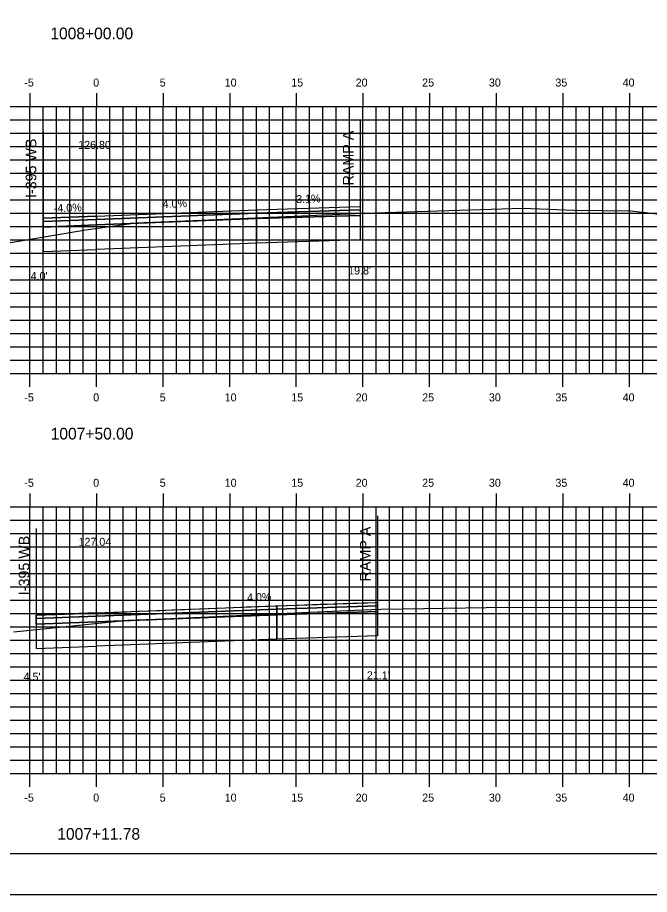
# Model space of a CAD drawing. Extents: x 851738 to 851910, y 365624 to 365734.
# Drawn here: x 851815.6 to 851863, y 365624 to 365689.7 of the extents above; entities that cross this region are included whole.
import ezdxf

# ---------------------------------------------------------------- set-up
doc = ezdxf.new("R2010")
doc.units = 0
for name, color, linetype in [('ANNOTATION', 7, 'Continuous'), ('BORDER', 7, 'Continuous'), ('D_Roadway_Centerline', 7, 'Continuous'), ('D_Roadway_Centerline_Text', 7, 'Continuous'), ('D_Roadway_Edge_Shoulder', 7, 'Continuous'), ('D_Roadway_Edge_TW', 7, 'Continuous'), ('D_Roadway_FinishedGrade', 7, 'Continuous'), ('D_Roadway_Pavement', 7, 'Continuous'), ('D_Roadway_SubGrade', 7, 'Continuous'), ('D_Text_Standard', 7, 'Continuous'), ('H_V ANNOTATION', 7, 'Continuous'), ('M_Roadway_Centerline', 7, 'Continuous'), ('MAJOR', 7, 'Continuous'), ('MINOR', 7, 'Continuous'), ('PLOT BOUNDARY', 7, 'Continuous'), ('S_Roadway_Centerline', 7, 'Continuous')]:
    doc.layers.add(name, color=color, linetype=linetype)

msp = doc.modelspace()

# ---------------------------------------------------------------- linework, layer by layer
at = {"layer": 'BORDER'}
msp.add_lwpolyline([(851746.522, 365627.027), (851906.522, 365627.027), (851906.522, 365732.027), (851746.522, 365732.027)], close=True, dxfattribs=at)
at = {"layer": 'D_Roadway_Centerline'}
for points in [[(851817.522, 365674.663), (851817.522, 365674.663), (851821.522, 365674.823), (851821.528, 365674.823), (851833.522, 365675.294), (851841.32, 365675.536)], [(851817.001, 365644.893), (851819.848, 365645.005), (851821.522, 365645.071), (851821.93, 365645.087), (851821.995, 365645.09), (851823.785, 365645.16), (851824.146, 365645.174), (851824.644, 365645.194), (851826.3, 365645.26), (851827.19, 365645.295), (851827.835, 365645.32), (851828.153, 365645.333), (851828.459, 365645.345), (851829.366, 365645.381), (851830.621, 365645.43), (851832.354, 365645.499), (851832.787, 365645.516), (851834.936, 365645.601), (851834.957, 365645.602), (851834.973, 365645.603), (851835.071, 365645.606), (851836.662, 365645.66), (851837.131, 365645.676), (851838.347, 365645.717), (851839.308, 365645.748), (851840.038, 365645.773), (851841.49, 365645.819), (851841.736, 365645.827), (851842.605, 365645.855)]]:
    msp.add_lwpolyline(points, dxfattribs=at)
at = {"layer": 'D_Roadway_Edge_Shoulder'}
for points in [[(851821.522, 365674.823), (851817.522, 365674.663), (851817.522, 365674.413), (851821.522, 365674.573)], [(851821.522, 365645.071), (851817.001, 365644.893), (851817.001, 365644.643), (851821.522, 365644.821)]]:
    msp.add_lwpolyline(points, close=True, dxfattribs=at)
at = {"layer": 'D_Roadway_Edge_TW'}
for points in [[(851833.522, 365675.294), (851841.32, 365675.536), (851841.32, 365675.286), (851833.522, 365675.044)], [(851821.522, 365674.823), (851833.522, 365675.294), (851833.522, 365675.044), (851821.522, 365674.573)], [(851835.071, 365645.606), (851842.605, 365645.855), (851842.605, 365645.605), (851835.071, 365645.356)], [(851821.522, 365645.071), (851835.071, 365645.606), (851835.071, 365645.356), (851821.522, 365644.821)]]:
    msp.add_lwpolyline(points, close=True, dxfattribs=at)
at = {"layer": 'D_Roadway_FinishedGrade'}
for p, q in [((851841.32, 365675.536), (851841.32, 365675.286)), ((851821.522, 365674.823), (851821.522, 365674.573)), ((851833.522, 365675.294), (851833.522, 365675.044)), ((851817.522, 365674.663), (851817.522, 365674.413)), ((851842.605, 365645.855), (851842.605, 365645.605)), ((851835.071, 365645.606), (851835.071, 365645.356)), ((851817.001, 365644.893), (851817.001, 365644.643)), ((851821.522, 365645.071), (851821.522, 365644.821))]:
    msp.add_line(p, q, dxfattribs=at)
at = {"layer": 'D_Roadway_Pavement'}
for points in [[(851821.522, 365674.573), (851833.522, 365675.044), (851833.522, 365674.627), (851821.522, 365674.156)], [(851833.522, 365675.044), (851841.32, 365675.286), (851841.32, 365674.869), (851833.522, 365674.627)], [(851821.522, 365674.573), (851817.522, 365674.413), (851817.522, 365673.996), (851821.522, 365674.156)], [(851821.522, 365644.821), (851835.071, 365645.356), (851835.071, 365644.939), (851821.522, 365644.404)], [(851835.071, 365645.356), (851842.605, 365645.605), (851842.605, 365645.189), (851835.071, 365644.939)], [(851821.522, 365644.821), (851817.001, 365644.643), (851817.001, 365644.226), (851821.522, 365644.404)]]:
    msp.add_lwpolyline(points, close=True, dxfattribs=at)
at = {"layer": 'D_Roadway_SubGrade'}
for p, q in [((851841.32, 365682.033), (851841.32, 365673.036)), ((851817.522, 365681.16), (851817.522, 365672.163)), ((851842.605, 365652.352), (851842.605, 365643.355)), ((851817.001, 365651.39), (851817.001, 365642.393))]:
    msp.add_line(p, q, dxfattribs=at)
for points in [[(851833.522, 365674.627), (851841.32, 365674.869), (851841.32, 365673.036), (851833.522, 365672.794)], [(851821.522, 365674.156), (851817.522, 365673.996), (851817.522, 365674.496), (851817.522, 365674.663), (851817.522, 365672.163), (851821.522, 365672.323)], [(851821.522, 365674.156), (851833.522, 365674.627), (851833.522, 365672.794), (851821.522, 365672.323)], [(851835.071, 365644.939), (851842.605, 365645.189), (851842.605, 365643.355), (851835.071, 365643.106)], [(851821.522, 365644.404), (851817.001, 365644.226), (851817.001, 365644.726), (851817.001, 365644.893), (851817.001, 365642.393), (851821.522, 365642.571)], [(851821.522, 365644.404), (851835.071, 365644.939), (851835.071, 365643.106), (851821.522, 365642.571)]]:
    msp.add_lwpolyline(points, close=True, dxfattribs=at)
at = {"layer": 'MAJOR'}
for p, q in [((851816.522, 365684.029), (851816.522, 365683.027)), ((851821.522, 365684.029), (851821.522, 365683.027)), ((851826.522, 365684.029), (851826.522, 365683.027)), ((851831.522, 365684.029), (851831.522, 365683.027)), ((851836.522, 365684.029), (851836.522, 365683.027)), ((851841.522, 365684.029), (851841.522, 365683.027)), ((851846.522, 365684.029), (851846.522, 365683.027)), ((851851.522, 365684.029), (851851.522, 365683.027)), ((851856.522, 365684.029), (851856.522, 365683.027)), ((851861.522, 365684.029), (851861.522, 365683.027)), ((851751.522, 365683.027), (851891.522, 365683.027)), ((851751.522, 365683.027), (851891.522, 365683.027)), ((851816.522, 365663.027), (851816.522, 365683.027)), ((851821.522, 365663.027), (851821.522, 365683.027)), ((851826.522, 365663.027), (851826.522, 365683.027)), ((851831.522, 365663.027), (851831.522, 365683.027)), ((851836.522, 365663.027), (851836.522, 365683.027)), ((851841.522, 365663.027), (851841.522, 365683.027)), ((851846.522, 365663.027), (851846.522, 365683.027)), ((851851.522, 365663.027), (851851.522, 365683.027)), ((851856.522, 365663.027), (851856.522, 365683.027)), ((851861.522, 365663.027), (851861.522, 365683.027)), ((851751.522, 365678.027), (851891.522, 365678.027)), ((851751.522, 365673.027), (851891.522, 365673.027)), ((851751.522, 365668.027), (851891.522, 365668.027)), ((851751.522, 365663.027), (851891.522, 365663.027)), ((851751.522, 365663.027), (851891.522, 365663.027)), ((851816.522, 365662.025), (851816.522, 365663.027)), ((851821.522, 365662.025), (851821.522, 365663.027)), ((851826.522, 365662.025), (851826.522, 365663.027)), ((851831.522, 365662.025), (851831.522, 365663.027)), ((851836.522, 365662.025), (851836.522, 365663.027)), ((851841.522, 365662.025), (851841.522, 365663.027)), ((851846.522, 365662.025), (851846.522, 365663.027)), ((851851.522, 365662.025), (851851.522, 365663.027)), ((851856.522, 365662.025), (851856.522, 365663.027)), ((851861.522, 365662.025), (851861.522, 365663.027)), ((851816.522, 365654.029), (851816.522, 365653.027)), ((851821.522, 365654.029), (851821.522, 365653.027)), ((851826.522, 365654.029), (851826.522, 365653.027)), ((851831.522, 365654.029), (851831.522, 365653.027)), ((851836.522, 365654.029), (851836.522, 365653.027)), ((851841.522, 365654.029), (851841.522, 365653.027)), ((851846.522, 365654.029), (851846.522, 365653.027)), ((851851.522, 365654.029), (851851.522, 365653.027)), ((851856.522, 365654.029), (851856.522, 365653.027)), ((851861.522, 365654.029), (851861.522, 365653.027)), ((851751.522, 365653.027), (851891.522, 365653.027)), ((851751.522, 365653.027), (851891.522, 365653.027)), ((851816.522, 365633.027), (851816.522, 365653.027)), ((851821.522, 365633.027), (851821.522, 365653.027)), ((851826.522, 365633.027), (851826.522, 365653.027)), ((851831.522, 365633.027), (851831.522, 365653.027)), ((851836.522, 365633.027), (851836.522, 365653.027)), ((851841.522, 365633.027), (851841.522, 365653.027)), ((851846.522, 365633.027), (851846.522, 365653.027)), ((851851.522, 365633.027), (851851.522, 365653.027)), ((851856.522, 365633.027), (851856.522, 365653.027)), ((851861.522, 365633.027), (851861.522, 365653.027)), ((851751.522, 365648.027), (851891.522, 365648.027)), ((851751.522, 365643.027), (851891.522, 365643.027)), ((851751.522, 365638.027), (851891.522, 365638.027)), ((851751.522, 365633.027), (851891.522, 365633.027)), ((851751.522, 365633.027), (851891.522, 365633.027)), ((851816.522, 365632.025), (851816.522, 365633.027)), ((851821.522, 365632.025), (851821.522, 365633.027)), ((851826.522, 365632.025), (851826.522, 365633.027)), ((851831.522, 365632.025), (851831.522, 365633.027)), ((851836.522, 365632.025), (851836.522, 365633.027)), ((851841.522, 365632.025), (851841.522, 365633.027)), ((851846.522, 365632.025), (851846.522, 365633.027)), ((851851.522, 365632.025), (851851.522, 365633.027)), ((851856.522, 365632.025), (851856.522, 365633.027)), ((851861.522, 365632.025), (851861.522, 365633.027))]:
    msp.add_line(p, q, dxfattribs=at)
at = {"layer": 'MINOR'}
for p, q in [((851817.522, 365663.027), (851817.522, 365683.027)), ((851818.522, 365663.027), (851818.522, 365683.027)), ((851819.522, 365663.027), (851819.522, 365683.027)), ((851820.522, 365663.027), (851820.522, 365683.027)), ((851822.522, 365663.027), (851822.522, 365683.027)), ((851823.522, 365663.027), (851823.522, 365683.027)), ((851824.522, 365663.027), (851824.522, 365683.027)), ((851825.522, 365663.027), (851825.522, 365683.027)), ((851827.522, 365663.027), (851827.522, 365683.027)), ((851828.522, 365663.027), (851828.522, 365683.027)), ((851829.522, 365663.027), (851829.522, 365683.027)), ((851830.522, 365663.027), (851830.522, 365683.027)), ((851832.522, 365663.027), (851832.522, 365683.027)), ((851833.522, 365663.027), (851833.522, 365683.027)), ((851834.522, 365663.027), (851834.522, 365683.027)), ((851835.522, 365663.027), (851835.522, 365683.027)), ((851837.522, 365663.027), (851837.522, 365683.027)), ((851838.522, 365663.027), (851838.522, 365683.027)), ((851839.522, 365663.027), (851839.522, 365683.027)), ((851840.522, 365663.027), (851840.522, 365683.027)), ((851842.522, 365663.027), (851842.522, 365683.027)), ((851843.522, 365663.027), (851843.522, 365683.027)), ((851844.522, 365663.027), (851844.522, 365683.027)), ((851845.522, 365663.027), (851845.522, 365683.027)), ((851847.522, 365663.027), (851847.522, 365683.027)), ((851848.522, 365663.027), (851848.522, 365683.027)), ((851849.522, 365663.027), (851849.522, 365683.027)), ((851850.522, 365663.027), (851850.522, 365683.027)), ((851852.522, 365663.027), (851852.522, 365683.027)), ((851853.522, 365663.027), (851853.522, 365683.027)), ((851854.522, 365663.027), (851854.522, 365683.027)), ((851855.522, 365663.027), (851855.522, 365683.027)), ((851857.522, 365663.027), (851857.522, 365683.027)), ((851858.522, 365663.027), (851858.522, 365683.027)), ((851859.522, 365663.027), (851859.522, 365683.027)), ((851860.522, 365663.027), (851860.522, 365683.027)), ((851862.522, 365663.027), (851862.522, 365683.027)), ((851751.522, 365682.027), (851891.522, 365682.027)), ((851751.522, 365681.027), (851891.522, 365681.027)), ((851751.522, 365680.027), (851891.522, 365680.027)), ((851751.522, 365679.027), (851891.522, 365679.027)), ((851751.522, 365677.027), (851891.522, 365677.027)), ((851751.522, 365676.027), (851891.522, 365676.027)), ((851751.522, 365675.027), (851891.522, 365675.027)), ((851751.522, 365674.027), (851891.522, 365674.027)), ((851751.522, 365672.027), (851891.522, 365672.027)), ((851751.522, 365671.027), (851891.522, 365671.027)), ((851751.522, 365670.027), (851891.522, 365670.027)), ((851751.522, 365669.027), (851891.522, 365669.027)), ((851751.522, 365667.027), (851891.522, 365667.027)), ((851751.522, 365666.027), (851891.522, 365666.027)), ((851751.522, 365665.027), (851891.522, 365665.027)), ((851751.522, 365664.027), (851891.522, 365664.027)), ((851817.522, 365633.027), (851817.522, 365653.027)), ((851818.522, 365633.027), (851818.522, 365653.027)), ((851819.522, 365633.027), (851819.522, 365653.027)), ((851820.522, 365633.027), (851820.522, 365653.027)), ((851822.522, 365633.027), (851822.522, 365653.027)), ((851823.522, 365633.027), (851823.522, 365653.027)), ((851824.522, 365633.027), (851824.522, 365653.027)), ((851825.522, 365633.027), (851825.522, 365653.027)), ((851827.522, 365633.027), (851827.522, 365653.027)), ((851828.522, 365633.027), (851828.522, 365653.027)), ((851829.522, 365633.027), (851829.522, 365653.027)), ((851830.522, 365633.027), (851830.522, 365653.027)), ((851832.522, 365633.027), (851832.522, 365653.027)), ((851833.522, 365633.027), (851833.522, 365653.027)), ((851834.522, 365633.027), (851834.522, 365653.027)), ((851835.522, 365633.027), (851835.522, 365653.027)), ((851837.522, 365633.027), (851837.522, 365653.027)), ((851838.522, 365633.027), (851838.522, 365653.027)), ((851839.522, 365633.027), (851839.522, 365653.027)), ((851840.522, 365633.027), (851840.522, 365653.027)), ((851842.522, 365633.027), (851842.522, 365653.027)), ((851843.522, 365633.027), (851843.522, 365653.027)), ((851844.522, 365633.027), (851844.522, 365653.027)), ((851845.522, 365633.027), (851845.522, 365653.027)), ((851847.522, 365633.027), (851847.522, 365653.027)), ((851848.522, 365633.027), (851848.522, 365653.027)), ((851849.522, 365633.027), (851849.522, 365653.027)), ((851850.522, 365633.027), (851850.522, 365653.027)), ((851852.522, 365633.027), (851852.522, 365653.027)), ((851853.522, 365633.027), (851853.522, 365653.027)), ((851854.522, 365633.027), (851854.522, 365653.027)), ((851855.522, 365633.027), (851855.522, 365653.027)), ((851857.522, 365633.027), (851857.522, 365653.027)), ((851858.522, 365633.027), (851858.522, 365653.027)), ((851859.522, 365633.027), (851859.522, 365653.027)), ((851860.522, 365633.027), (851860.522, 365653.027)), ((851862.522, 365633.027), (851862.522, 365653.027)), ((851751.522, 365652.027), (851891.522, 365652.027)), ((851751.522, 365651.027), (851891.522, 365651.027)), ((851751.522, 365650.027), (851891.522, 365650.027)), ((851751.522, 365649.027), (851891.522, 365649.027)), ((851751.522, 365647.027), (851891.522, 365647.027)), ((851751.522, 365646.027), (851891.522, 365646.027)), ((851751.522, 365645.027), (851891.522, 365645.027)), ((851751.522, 365644.027), (851891.522, 365644.027)), ((851751.522, 365642.027), (851891.522, 365642.027)), ((851751.522, 365641.027), (851891.522, 365641.027)), ((851751.522, 365640.027), (851891.522, 365640.027)), ((851751.522, 365639.027), (851891.522, 365639.027)), ((851751.522, 365637.027), (851891.522, 365637.027)), ((851751.522, 365636.027), (851891.522, 365636.027)), ((851751.522, 365635.027), (851891.522, 365635.027)), ((851751.522, 365634.027), (851891.522, 365634.027))]:
    msp.add_line(p, q, dxfattribs=at)
at = {"layer": 'PLOT BOUNDARY'}
msp.add_lwpolyline([(851738.429, 365623.968), (851908.429, 365623.968), (851908.429, 365733.968), (851738.429, 365733.968)], close=True, dxfattribs=at)
at = {"layer": 'S_Roadway_Centerline'}
for points in [[(851811.196, 365672.193), (851820.737, 365673.799), (851824.488, 365674.319), (851827.622, 365674.443), (851841.542, 365675.033), (851841.601, 365675.033), (851841.604, 365675.035), (851841.621, 365675.036), (851853.529, 365675.409), (851857.354, 365675.261), (851861.611, 365675.209), (851863.374, 365675.015), (851874.012, 365673.524), (851877.919, 365672.999), (851880.529, 365672.534), (851891.522, 365669.169)], [(851815.305, 365643.654), (851816.061, 365643.732), (851818.751, 365644.002), (851823.874, 365644.532), (851825.943, 365644.611), (851829.955, 365644.773), (851834.139, 365644.987), (851841.516, 365645.299), (851842.856, 365645.354), (851846.07, 365645.415), (851852.342, 365645.492), (851865.787, 365645.478), (851866.215, 365645.397), (851873.421, 365644.59), (851878.907, 365643.882), (851887.151, 365642.728), (851891.522, 365642.031)]]:
    msp.add_lwpolyline(points, dxfattribs=at)

# ---------------------------------------------------------------- texts
at = {"layer": 'ANNOTATION'}
for s, height, rotation, p in [('RAMP A', 0.8, 90, (851840.813, 365677.117)), ('I-395 WB', 0.8, 90, (851817.015, 365676.17)), ('4.0%', 0.6, 2.24769, (851826.502, 365675.419)), ('3.1%', 0.6, 1.77767, (851836.518, 365675.787)), ('-4.0%', 0.6, 2.29041, (851818.338, 365675.096)), ('RAMP A', 0.8, 90, (851842.098, 365647.436)), ('I-395 WB', 0.8, 90, (851816.494, 365646.4)), ('4.0%', 0.6, 2.27856, (851832.838, 365645.918))]:
    msp.add_text(s, height=height, rotation=rotation, dxfattribs=at).set_placement(p)
at = {"layer": 'D_Roadway_Centerline'}
for s, p in [('C', (851821.517, 365674.823)), ('L', (851821.522, 365674.815))]:
    msp.add_text(s, height=0.0146, dxfattribs=at).set_placement(p)
at = {"layer": 'D_Roadway_Centerline_Text'}
for s, p in [('126.80', (851820.152, 365679.855)), ('127.04', (851820.179, 365650.103))]:
    msp.add_text(s, height=0.6, dxfattribs=at).set_placement(p)
at = {"layer": 'D_Text_Standard'}
for s, p in [("19.8'", (851840.413, 365670.439)), ("4.0'", (851816.588, 365670.027)), ("4.5'", (851816.057, 365639.989)), ("21.1'", (851841.816, 365640.096))]:
    msp.add_text(s, height=0.6, dxfattribs=at).set_placement(p)
at = {"layer": 'H_V ANNOTATION'}
for s, height, p in [('1008+00.00', 0.875, (851818.065, 365688.07)), ('-5', 0.6, (851816.113, 365684.527)), ('0', 0.6, (851821.281, 365684.527)), ('5', 0.6, (851826.273, 365684.527)), ('10', 0.6, (851831.148, 365684.527)), ('15', 0.6, (851836.14, 365684.527)), ('20', 0.6, (851840.976, 365684.527)), ('25', 0.6, (851845.968, 365684.527)), ('30', 0.6, (851850.971, 365684.527)), ('35', 0.6, (851855.963, 365684.527)), ('40', 0.6, (851861.008, 365684.527)), ('-5', 0.6, (851816.113, 365660.927)), ('0', 0.6, (851821.281, 365660.927)), ('5', 0.6, (851826.273, 365660.927)), ('10', 0.6, (851831.148, 365660.927)), ('15', 0.6, (851836.14, 365660.927)), ('20', 0.6, (851840.976, 365660.927)), ('25', 0.6, (851845.968, 365660.927)), ('30', 0.6, (851850.971, 365660.927)), ('35', 0.6, (851855.963, 365660.927)), ('40', 0.6, (851861.008, 365660.927)), ('1007+50.00', 0.875, (851818.089, 365658.07)), ('-5', 0.6, (851816.113, 365654.527)), ('0', 0.6, (851821.281, 365654.527)), ('5', 0.6, (851826.273, 365654.527)), ('10', 0.6, (851831.148, 365654.527)), ('15', 0.6, (851836.14, 365654.527)), ('20', 0.6, (851840.976, 365654.527)), ('25', 0.6, (851845.968, 365654.527)), ('30', 0.6, (851850.971, 365654.527)), ('35', 0.6, (851855.963, 365654.527)), ('40', 0.6, (851861.008, 365654.527)), ('-5', 0.6, (851816.113, 365630.927)), ('0', 0.6, (851821.281, 365630.927)), ('5', 0.6, (851826.273, 365630.927)), ('10', 0.6, (851831.148, 365630.927)), ('15', 0.6, (851836.14, 365630.927)), ('20', 0.6, (851840.976, 365630.927)), ('25', 0.6, (851845.968, 365630.927)), ('30', 0.6, (851850.971, 365630.927)), ('35', 0.6, (851855.963, 365630.927)), ('40', 0.6, (851861.008, 365630.927)), ('1007+11.78', 0.875, (851818.584, 365628.07))]:
    msp.add_text(s, height=height, dxfattribs=at).set_placement(p)
at = {"layer": 'M_Roadway_Centerline'}
for s, p in [('C', (851841.599, 365675.035)), ('L', (851841.604, 365675.028))]:
    msp.add_text(s, height=0.0146, dxfattribs=at).set_placement(p)

doc.saveas('drawing.dxf')
